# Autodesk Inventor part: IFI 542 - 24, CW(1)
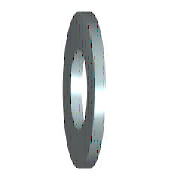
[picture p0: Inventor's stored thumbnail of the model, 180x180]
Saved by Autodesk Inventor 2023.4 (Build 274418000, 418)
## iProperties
Created: 2022-02
Part Number: IFI 542 - 24, CW(1)
Material: Acier, doux
Description: Rondelle circulaire
Document SubType Name: Modeling
Standard: IFI 542
Designer: bruno
Standards Organization: ANSI
Language: fr-FR
Size Designation: 24
Categories: <MemberInstance><Categories><Category DisplayName="Visserie" InternalName="e4da775c-781d-43d5-af7c-5136215cf5a6" Mnemonic="FSTN"><Category DisplayName="Rondelle
Density: 7.85 g/cm^3
Appearance: Semi-poli
IsCustomPart: 0
Author: bruno
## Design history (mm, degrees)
body "Solid1"
sketch "Esquisse"
  geometry: C1 r 25 at (0, 0); C2 r 13 at (0, 0); 1 further point
  constraints: 2 centre point, 2 coincident
  dimensions: "d0" = 26 diameter of C2 (= SD1); "d1" = 50 diameter of C1 (= SD2)
extrude "Corps" new body sketch "Esquisse" distance "d2" = 4.6 (= SD); taper "d3" = 0 deg
workaxis "Work Axis1"
workplane "Work Plane1"
other parameters: "SD1" = 26 [user parameter; used in 1 equation term], "SD2" = 50 [user parameter; used in 1 equation term], "SD" = 4.6 [user parameter; used in 1 equation term], "d4" = 0, "d5" = 0, "d6" = 0, "d7" = 0, "NND" = 24 [user parameter]
